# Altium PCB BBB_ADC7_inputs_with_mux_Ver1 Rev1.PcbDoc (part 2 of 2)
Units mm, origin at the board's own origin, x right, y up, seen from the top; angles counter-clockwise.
Board outline 219.96 x 100 mm, 2 copper layers (TopLayer, BottomLayer), stack 1.571 mm thick; 181 components, 118 nets, 709 pads, 266 vias.
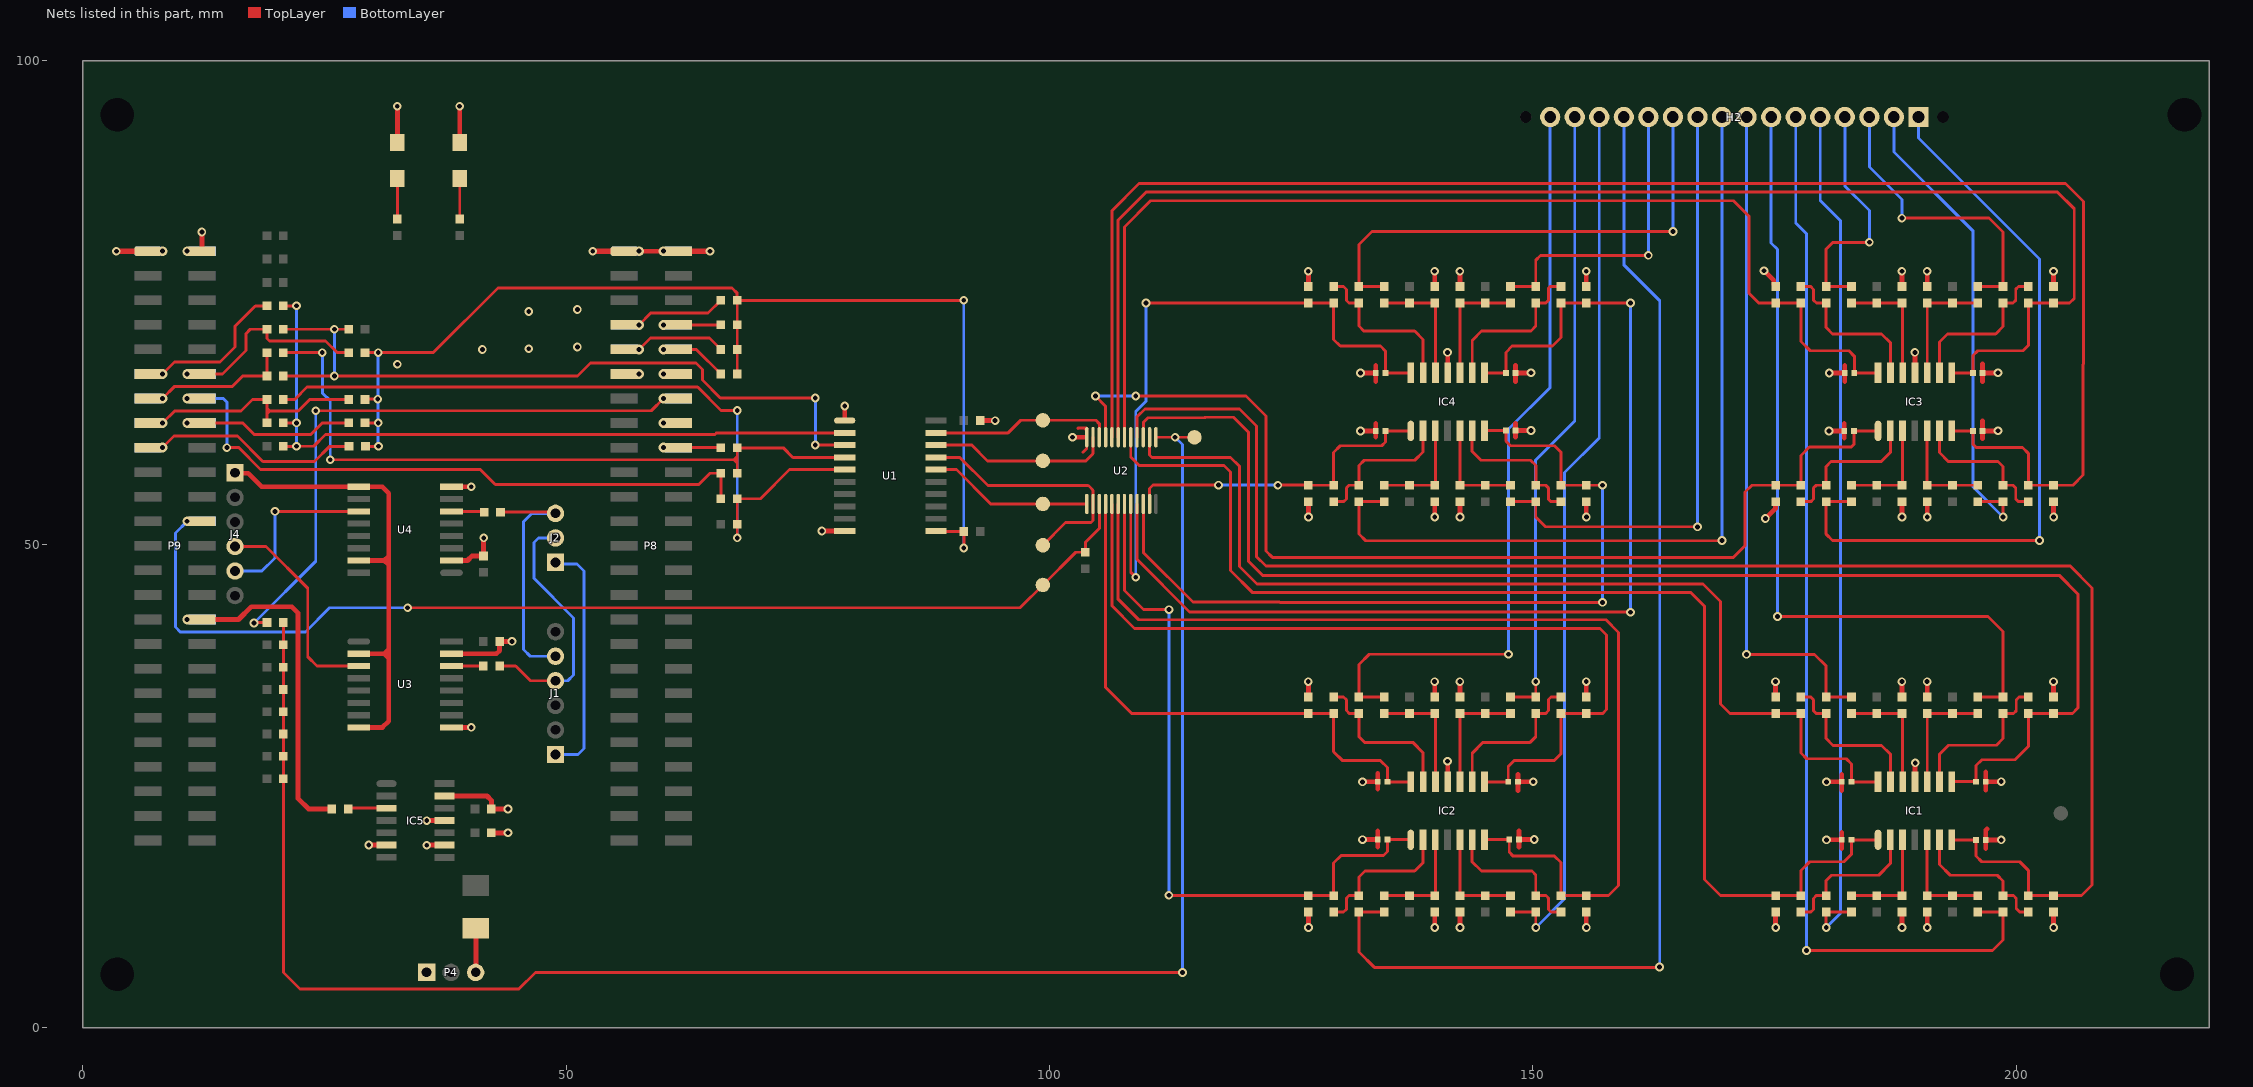
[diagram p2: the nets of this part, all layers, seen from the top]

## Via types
v1: diameter 0.9, hole 0.5, TopLayer to BottomLayer, tented both sides, 166 vias
v2: diameter 1.016, hole 0.508, TopLayer to BottomLayer, 100 vias

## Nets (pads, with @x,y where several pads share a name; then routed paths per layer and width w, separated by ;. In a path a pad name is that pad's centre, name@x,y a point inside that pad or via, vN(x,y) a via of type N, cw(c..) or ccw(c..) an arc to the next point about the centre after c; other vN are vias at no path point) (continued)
BBB_GND: C1.2 C2.2 C3.2 C4.2 C5.2 C6.2 C7.2 C8.2 C9.2 C10.2 C11.2 C12.2 C13.2 C14.2 C15.2 C16.2 C17.2 C18.2 C19.2 C20.2 C21.2 IC1.11 IC2.11 IC3.11 IC4.11 IC5.6 IC5.9 IC5.11 IC5.13 LED1.K LED2.K P4.1 P8.1 P8.2 P9.1 P9.2 R1.2 R6.2 R7.2 R11.2 R12.2 R17.2 R18.2 R22.2 R25.2 R27.2 R33.2 R35.2 R45.2 R46.2 R47.2 R48.2 R49.2 R50.2 R51.2 R52.2 R57.1 R62.1 R63.1 R68.2 R69.1 R74.1 R75.1 R80.2 R84.1 R85.1 R92.1 R93.1 U1.1 U1.10 U2.12 U3.9 U3.15 U4.2 U4.8 | length 180
  TopLayer w0.3: 102.93,61.975 102.958,62.004 103.504,62.004 ; 103.475,59.51 103.855,59.889 U2.12@103.855,61.059 103.855,61.654 ccw(c103.504,61.654) 103.504,62.004 ; U2.12@103.868,61.943 103.806,62.004 103.504,62.004 ; v1(126.769,35.777) v1@126.778,35.769 ; v1(126.769,78.233) v1@126.778,78.225 ; v1@126.778,10.358 v1(126.786,10.35) ; v1@126.778,52.814 v1(126.786,52.806) ; v1(132.167,61.704) v1@132.175,61.712 ; v1(132.167,67.711) v1@132.175,67.719 ; v1(132.372,19.436) v1@132.381,19.444 ; v1(132.372,25.408) v1@132.381,25.416 ; v1(139.839,35.777) v1@139.847,35.769 ; v1(139.839,78.233) v1@139.847,78.225 ; v1@139.847,10.358 v1(139.855,10.35) ; v1@139.847,52.814 v1(139.855,52.806) ; v1(142.453,35.777) v1@142.461,35.769 ; v1(142.453,78.233) v1@142.461,78.225 ; v1@142.461,10.358 v1(142.469,10.35) ; v1@142.461,52.814 v1(142.469,52.806) ; v1@149.795,61.748 v1(149.803,61.756) ; v1@149.795,67.719 v1(149.803,67.727) ; v1@150.037,25.416 v1(150.045,25.424) ; v1@150.137,19.444 v1(150.145,19.453) ; v1(155.522,35.777) v1@155.53,35.769 ; v1(155.522,78.233) v1@155.53,78.225 ; v1@155.53,10.358 v1(155.539,10.35) ; v1@155.53,52.814 v1(155.539,52.806) ; v1(175.106,35.777) v1@175.114,35.769 ; v1@175.114,10.358 v1(175.122,10.35) ; v1(180.367,19.408) v1@180.375,19.416 ; v1(180.367,25.408) v1@180.375,25.416 ; v1(180.628,61.711) v1@180.637,61.719 ; v1(180.667,67.704) v1@180.675,67.712 ; v1(188.175,35.777) v1@188.183,35.769 ; v1(188.175,78.233) v1@188.183,78.225 ; v1@188.183,10.358 v1(188.192,10.35) ; v1@188.183,52.814 v1(188.192,52.806) ; v1(190.789,35.777) v1@190.797,35.769 ; v1(190.789,78.233) v1@190.797,78.225 ; v1@190.797,10.358 v1(190.806,10.35) ; v1@190.797,52.814 v1(190.806,52.806) ; v1@198.106,61.719 v1(198.114,61.727) ; v1@198.106,67.719 v1(198.114,67.727) ; v1@198.437,19.402 v1(198.445,19.411) ; v1@198.437,25.428 v1(198.445,25.437) ; v1(203.859,35.777) v1@203.867,35.769 ; v1(203.859,78.233) v1@203.867,78.225 ; v1@203.867,10.358 v1(203.875,10.35) ; v1@203.867,52.814 v1(203.875,52.806)
  TopLayer w0.5: v1(12.313,82.296) 12.325,82.284 P9.2@12.325,80.305 ; v1@29.592,18.877 IC5.6@31.417,18.877 ; v1(32.524,95.3) 32.537,95.286 LED1.K@32.537,91.562 ; v1@35.592,18.867 IC5.9@37.417,18.867 ; v1@35.592,21.407 IC5.11@37.417,21.407 ; IC5.13@37.417,23.947 41.813,23.947 42.266,23.495 C20.2@42.266,22.606 v1(43.994,22.606) ; U3.9@38.139,31.039 40.164,31.039 v1(40.175,31.05) ; U3.15@38.139,38.659 42.786,38.659 43.116,38.989 C18.2@43.116,39.929 44.384,39.929 v1(44.399,39.944) ; U4.2@38.139,48.311 39.796,48.311 40.267,48.782 C19.2@41.456,48.782 41.456,50.631 v1(41.475,50.65) ; U4.8@38.139,55.931 40.164,55.931 v1(40.175,55.942) ; v1(38.982,95.3) 38.996,95.286 LED2.K@38.996,91.562 ; C21.2@42.266,20.137 43.984,20.137 v1(43.994,20.147) ; P8.1@56.001,80.305 v2(57.531,80.305) v2(60.071,80.305) P8.2@61.601,80.305 ; v1(76.45,51.358) U1.10@78.812,51.358 ; U1.1@78.812,62.788 78.812,64.287 v1(78.825,64.3) ; C17.2@92.835,62.788 94.362,62.788 v1(94.375,62.775) ; v1(102.374,61.059) U2.12@103.75,61.059 ; v1@126.778,10.358 R69.1@126.778,11.939 ; R12.2@126.778,34.188 v1@126.778,35.769 ; v1@126.778,52.814 R51.2@126.778,54.395 ; R47.2@126.778,76.644 v1@126.778,78.225 ; v1@132.175,61.712 C9.2@133.756,61.712 ; v1@132.175,67.719 C12.2@133.756,67.719 ; v1@132.381,19.444 C13.2@133.962,19.444 ; v1@132.381,25.416 C16.2@133.962,25.416 ; 133.756,61.075 C9.2@133.756,61.712 ; 133.756,62.472 C9.2@133.756,61.712 ; 133.756,66.833 C12.2@133.756,67.719 ; 133.756,68.48 C12.2@133.756,67.719 ; 133.962,18.684 C13.2@133.962,19.444 ; 133.962,20.331 C13.2@133.962,19.444 ; 133.962,24.655 C16.2@133.962,25.416 ; 133.962,26.302 C16.2@133.962,25.416 ; v1@139.847,10.358 R74.1@139.847,11.939 ; R17.2@139.847,34.188 v1@139.847,35.769 ; v1@139.847,52.814 R92.1@139.847,54.395 ; R33.2@139.847,76.644 v1@139.847,78.225 ; v1(141.181,27.537) 141.191,27.527 IC2.11@141.191,25.416 ; v1(141.181,69.84) 141.191,69.83 IC4.11@141.191,67.719 ; v1@142.461,10.358 R75.1@142.461,11.939 ; R18.2@142.461,34.188 v1@142.461,35.769 ; v1@142.461,52.814 R93.1@142.461,54.395 ; R35.2@142.461,76.644 v1@142.461,78.225 ; 148.214,61.1 C10.2@148.214,61.748 ; 148.214,62.508 C10.2@148.214,61.748 ; 148.214,66.833 C11.2@148.214,67.719 ; 148.214,68.48 C11.2@148.214,67.719 ; 148.456,24.53 C15.2@148.456,25.416 ; 148.456,26.177 C15.2@148.456,25.416 ; 148.556,18.684 C14.2@148.556,19.444 ; 148.556,20.331 C14.2@148.556,19.444 ; v1@149.795,61.748 C10.2@148.214,61.748 ; v1@149.795,67.719 C11.2@148.214,67.719 ; v1@150.037,25.416 C15.2@148.456,25.416 ; v1@150.137,19.444 C14.2@148.556,19.444 ; v1@155.53,10.358 R80.2@155.53,11.939 ; R22.2@155.53,34.188 v1@155.53,35.769 ; v1@155.53,52.814 R52.2@155.53,54.395 ; R48.2@155.53,76.644 v1@155.53,78.225 ; v1(173.916,78.277) 174.914,77.279 174.914,76.844 R45.2@175.114,76.644 ; v1(174.054,52.644) 175.114,53.704 R49.2@175.114,54.395 R49.2@174.979,54.26 ; v1@175.114,10.358 R57.1@175.114,11.939 ; R1.2@175.114,34.188 v1@175.114,35.769 ; v1@180.375,19.416 C5.2@181.956,19.416 ; v1@180.375,25.416 C8.2@181.956,25.416 ; v1@180.637,61.719 C1.2@182.218,61.719 ; v1@180.675,67.712 C4.2@182.256,67.712 ; 181.956,18.53 C5.2@181.956,19.416 ; 181.956,20.177 C5.2@181.956,19.416 ; 181.956,24.53 C8.2@181.956,25.416 ; 181.956,26.177 C8.2@181.956,25.416 ; 182.218,60.975 C1.2@182.218,61.719 ; 182.218,62.48 C1.2@182.218,61.719 ; 182.256,66.826 C4.2@182.256,67.712 ; 182.256,68.472 C4.2@182.256,67.712 ; v1@188.183,10.358 R62.1@188.183,11.939 ; R6.2@188.183,34.188 v1@188.183,35.769 ; v1@188.183,52.814 R84.1@188.183,54.395 ; R25.2@188.183,76.644 v1@188.183,78.225 ; v1(189.517,69.84) 189.527,69.83 IC3.11@189.527,67.719 ; IC1.11@189.527,25.416 189.527,27.352 v1(189.55,27.375) ; v1@190.797,10.358 R63.1@190.797,11.939 ; R7.2@190.797,34.188 v1@190.797,35.769 ; v1@190.797,52.814 R85.1@190.797,54.395 ; R27.2@190.797,76.644 v1@190.797,78.225 ; 196.525,60.925 C2.2@196.525,61.719 ; 196.525,62.725 C2.2@196.525,61.719 ; 196.525,66.833 C3.2@196.525,67.719 ; 196.525,68.65 C3.2@196.525,67.719 ; 196.856,18.516 C6.2@196.856,19.402 ; 196.856,24.542 C7.2@196.856,25.428 ; 196.856,26.425 C7.2@196.856,25.428 ; 196.983,20.549 196.856,20.422 C6.2@196.856,19.402 ; v1@198.106,61.719 C2.2@196.525,61.719 ; v1@198.106,67.719 C3.2@196.525,67.719 ; v1@198.437,19.402 C6.2@196.856,19.402 ; v1@198.437,25.428 C7.2@196.856,25.428 ; v1@203.867,10.358 R68.2@203.867,11.939 ; R11.2@203.867,34.188 v1@203.867,35.769 ; v1@203.867,52.814 R50.2@203.867,54.395 ; R46.2@203.867,76.644 v1@203.867,78.225
  TopLayer w0.6: v1(3.473,80.305) P9.1@6.725,80.305 P9.1@6.755,80.305 ; v1(52.749,80.305) P8.1@56.001,80.305 ; P8.2@61.601,80.305 v1(64.883,80.305)
  other v1: 35.584,18.859 29.584,18.869 35.584,21.399 32.537,68.613 41.33,70.145 46.131,70.215 51.161,70.399 46.131,74.066 51.161,74.267
  other v2: 8.255,80.305 10.795,80.305
BBB_SEL0: R107.2 R108.2 R109.2 U1.2 | length 75.9
  TopLayer w0.3: R109.2@20.746,60.122 22.025,60.122 22.028,60.125 v1(22.1,60.125) 23.889,60.125 25.104,61.339 65.389,61.339 65.568,61.518 U1.2@78.812,61.518 ; R108.2@20.746,62.543 22.025,62.543 22.028,62.546 v1(22.1,62.546) ; R107.2@20.746,74.651 22.025,74.651 22.028,74.654 v1(22.1,74.654)
  BottomLayer w0.3: v1(22.1,60.125) v1(22.1,62.546) v1(22.1,74.654)
BBB_SEL1: R110.2 R111.2 R112.2 U1.3 | length 77.4
  TopLayer w0.3: R110.2@20.746,67.386 v1(26.025,67.386) 51.161,67.386 52.518,68.743 63.432,68.743 64.1,68.075 64.1,66.973 65.948,65.125 v1(75.775,65.125) ; R111.2@20.746,72.229 R112.2@27.689,72.229 ; v1(75.775,60.248) U1.3@78.812,60.248
  BottomLayer w0.3: v1(26.025,67.386) v1(26.025,72.225) ; v1(75.775,60.248) v1(75.775,65.125)
BBB_SEL2: R113.2 R114.2 R115.2 U1.4 | length 72.3
  TopLayer w0.3: R113.2@20.746,69.808 24.772,69.808 v1(24.775,69.811) ; v1(25.6,58.725) 25.608,58.733 67.36,58.733 ; R115.2@67.703,57.333 67.703,59.076 ; 67.703,58.39 67.36,58.733 ; U1.4@78.812,58.978 73.447,58.978 72.46,59.965 R114.2@67.703,59.965 67.703,59.076 ; 67.36,58.733 67.703,59.076
  BottomLayer w0.3: v1(24.775,69.811) 24.775,65.65 25.6,64.825 v1(25.6,58.725)
BBB_SEL3: R116.2 R117.2 R118.2 U1.5 | length 78.1
  TopLayer w0.3: R116.2@20.746,64.965 21.915,64.965 23.2,66.25 63.604,66.25 66.029,63.825 v1(67.7,63.825) ; v1(67.703,50.648) R118.2@67.703,52.07 R117.2@67.703,54.702 70.102,54.702 73.108,57.708 U1.5@78.812,57.708
  BottomLayer w0.3: v1(67.7,63.825) 67.703,63.822 v1(67.703,50.648)
EN6595_2: P8.8 R120.2 | length 4.4
  TopLayer w0.3: P8.8@61.601,72.685 R120.2@66.003,72.685
  other v2: 60.071,72.685
IN0: H2.1 R81.1 R82.1 | length 77.3
  TopLayer w0.3: R82.1@182.956,54.395 R81.1@180.342,54.395 180.342,51.033 181.007,50.368 v1(202.4,50.368)
  BottomLayer w0.3: H2.1@189.89,94.183 189.89,92.01 202.4,79.5 v1(202.4,50.368)
IN1: H2.2 R87.1 R88.1 | length 50.3
  TopLayer w0.3: R87.1@196.025,54.395 R88.1@198.639,54.395 198.639,52.814 v1(198.647,52.806)
  BottomLayer w0.3: H2.2@187.35,94.183 187.35,90.575 195.55,82.375 195.55,55.903 v1(198.647,52.806)
IN2: H2.3 R28.2 R30.1 | length 31.2
  TopLayer w0.3: v1(188.175,83.725) 197.2,83.725 198.639,82.286 R30.1@198.639,76.644 R28.2@196.025,76.644
  BottomLayer w0.3: H2.3@184.81,94.183 184.81,89.015 188.175,85.65 v1(188.175,83.725)
IN3: H2.4 R23.2 R24.2 | length 25.3
  TopLayer w0.3: R24.2@182.956,76.644 R23.2@180.342,76.644 180.342,78.225 180.334,78.233 180.334,80.509 181.05,81.225 v1(184.81,81.225)
  BottomLayer w0.3: H2.4@182.27,94.183 182.27,87.055 184.81,84.515 v1(184.81,81.225)
IN4: H2.5 R59.1 R60.1 | length 89.5
  TopLayer w0.3: v1(180.35,10.35) 180.342,10.358 R59.1@180.342,11.939 R60.1@182.956,11.939
  BottomLayer w0.3: H2.5@179.73,94.183 179.73,85.545 181.825,83.45 181.825,11.825 v1(180.35,10.35)
IN5: H2.6 R65.1 R66.1 | length 113
  TopLayer w0.3: v1(178.3,7.975) 197.55,7.975 198.639,9.064 R66.1@198.639,11.939 R65.1@196.025,11.939
  BottomLayer w0.3: H2.6@177.19,94.183 177.19,83.222 178.325,82.088 178.325,8 v1(178.3,7.975)
IN6: H2.7 R8.2 R9.1 | length 85.2
  TopLayer w0.3: v1(175.3,42.525) 197.075,42.525 198.639,40.961 198.639,34.39 198.437,34.188 R8.2@196.025,34.188
  BottomLayer w0.3: H2.7@174.65,94.183 174.65,81.15 175.3,80.5 v1(175.3,42.525)
IN7: H2.8 R3.2 R4.2 | length 70.2
  TopLayer w0.3: v1(172.1,38.6) 179.15,38.6 180.342,37.408 R3.2@180.342,34.188 R4.2@182.956,34.188
  BottomLayer w0.3: v1(172.1,38.6) 172.11,38.61 H2.8@172.11,94.183
IN8: H2.9 R89.1 R90.1 | length 87.6
  TopLayer w0.3: R90.1@134.619,54.395 R89.1@132.005,54.395 132.005,51.059 132.713,50.351 169.551,50.351 v1(169.575,50.375)
  BottomLayer w0.3: H2.9@169.57,94.183 169.57,50.38 v1(169.575,50.375)
IN9: H2.10 R95.1 R96.1 | length 63.7
  TopLayer w0.3: R95.1@147.689,54.395 R96.1@150.303,54.395 150.303,52.814 151.316,51.8 167.016,51.8 v1(167.025,51.791)
  BottomLayer w0.3: v1@167.03,51.791 H2.10@167.03,94.183
IN10: H2.11 R31.2 R32.2 | length 51.9
  TopLayer w0.3: R32.2@134.619,76.644 R31.2@132.005,76.644 132.005,81.005 133.35,82.35 v1(164.5,82.35)
  BottomLayer w0.3: H2.11@164.49,94.183 164.49,82.36 v1(164.5,82.35)
IN11: H2.12 R36.2 R38.1 | length 31.5
  TopLayer w0.3: R36.2@147.689,76.644 R38.1@150.303,76.644 150.303,79.378 150.8,79.875 v1(161.95,79.875)
  BottomLayer w0.3: v1(161.95,79.875) H2.12@161.95,94.183
IN12: H2.13 R71.1 R72.1 | length 128
  TopLayer w0.3: R72.1@134.619,11.939 R71.1@132.005,11.939 132.005,7.82 133.6,6.225 163.075,6.225 v1(163.1,6.25)
  BottomLayer w0.3: H2.13@159.41,94.183 159.41,78.895 163.125,75.18 163.125,6.275 v1(163.1,6.25)
IN13: H2.14 R77.1 R78.1 | length 90.8
  TopLayer w0.3: R77.1@147.689,11.939 R78.1@150.303,11.939 150.303,10.358 v1(150.311,10.35)
  BottomLayer w0.3: v1(150.311,10.35) 153.276,13.315 153.276,57.399 156.87,60.994 H2.14@156.87,94.183
IN14: H2.15 R19.2 R20.1 | length 64.3
  TopLayer w0.3: R19.2@147.689,34.188 R20.1@150.303,34.188 150.303,35.769 v1(150.294,35.777)
  BottomLayer w0.3: v1(150.294,35.777) 150.294,58.718 154.33,62.754 H2.15@154.33,94.183
IN15: H2.16 R14.2 R15.2 | length 79.2
  TopLayer w0.3: R15.2@134.619,34.188 R14.2@132.005,34.188 132.005,37.543 133.073,38.61 v1(147.485,38.61)
  BottomLayer w0.3: v1(147.485,38.61) 147.485,61.91 151.79,66.215 H2.16@151.79,94.183
LATCH1: R97.1 R119.1 R120.1 R121.1 R122.1 R123.1 R126.1 R128.1 R129.1 U1.11 | length 117.4
  TopLayer w0.3: R126.1@29.2,64.965 29.163,65.001 30.442,65.001 30.445,65.004 v1(30.517,65.004) ; R123.1@29.2,69.808 30.479,69.808 30.482,69.811 v1(30.554,69.811) 36.257,69.811 42.946,76.5 67.141,76.5 67.692,75.95 67.692,75.236 R119.1@67.703,75.225 ; R129.1@29.236,60.122 30.515,60.122 30.518,60.125 v1(30.59,60.125) ; R128.1@29.236,62.507 R128.1@29.2,62.543 30.479,62.543 30.482,62.546 v1(30.554,62.546) ; R122.1@67.703,67.605 R121.1@67.703,70.145 R120.1@67.703,72.685 R119.1@67.703,75.225 ; U1.11@88.264,51.358 88.305,51.317 R97.1@91.135,51.317 91.135,49.61 v1(91.125,49.6) ; v1(91.135,75.225) R119.1@67.703,75.225
  BottomLayer w0.3: v1(30.554,69.811) v1(30.554,62.546) 30.554,60.161 v1(30.59,60.125) ; v1(91.125,49.6) 91.125,75.216 v1(91.135,75.225)
NetD03_1: D03.1 P4.3 | length 4.5
  TopLayer w0.5: P4.3@40.665,5.729 D03.1@40.665,10.261
NetIC1_2: IC1.2 R58.1 R59.2 | length 15.4
  TopLayer w0.3: R58.1@177.728,11.939 178.756,11.939 179.025,12.208 179.025,13.35 179.314,13.639 R59.2@180.342,13.639 180.342,15.197 180.895,15.75 185.776,15.75 186.977,16.951 IC1.2@186.977,19.416
NetIC1_3: IC1.3 R60.2 R61.2 R62.2 | length 11
  TopLayer w0.3: R60.2@182.956,13.639 R61.2@185.57,13.639 R62.2@188.183,13.639 188.247,13.703 IC1.3@188.247,19.416
NetIC1_5: IC1.5 R63.2 R64.2 R65.2 | length 11
  TopLayer w0.3: IC1.5@190.787,19.416 190.787,13.65 R63.2@190.797,13.639 R64.2@193.411,13.639 R65.2@196.025,13.639
NetIC1_6: IC1.6 R66.2 R67.2 | length 15.3
  TopLayer w0.3: IC1.6@192.057,19.416 192.057,16.871 193.178,15.75 198.04,15.75 198.639,15.151 R66.2@198.639,13.639 199.713,13.639 200.003,13.35 200.003,12.301 200.364,11.939 R67.2@201.253,11.939
NetIC1_9: IC1.9 R9.2 R10.2 | length 16.7
  TopLayer w0.3: IC1.9@192.067,25.416 192.067,28.267 193,29.2 197.956,29.2 198.639,29.883 R9.2@198.639,32.488 199.721,32.488 200.003,32.769 200.003,33.891 200.3,34.188 R10.2@201.253,34.188
NetIC1_10: IC1.10 R7.1 R8.1 R39.1 | length 12.3
  TopLayer w0.3: IC1.10@190.797,25.416 190.797,32.488 R39.1@193.411,32.488 R8.1@196.025,32.488
NetIC1_12: IC1.12 R4.1 R5.1 R6.1 | length 12.3
  TopLayer w0.3: R4.1@182.956,32.488 R5.1@185.57,32.488 R6.1@188.183,32.488 188.257,32.414 IC1.12@188.257,25.416
NetIC1_13: IC1.13 R2.2 R3.1 | length 16.8
  TopLayer w0.3: R2.2@177.728,34.188 178.755,34.188 179.045,33.899 179.045,32.757 179.314,32.488 R3.1@180.342,32.488 180.342,29.883 181.05,29.175 186.075,29.175 186.987,28.263 IC1.13@186.987,25.416
NetIC2_2: IC2.2 R70.1 R71.2 | length 15.5
  TopLayer w0.3: R70.1@129.391,11.939 130.419,11.939 130.708,12.229 130.708,13.37 130.977,13.639 R71.2@132.005,13.639 132.005,15.555 132.625,16.175 137.775,16.175 138.641,17.041 IC2.2@138.641,19.416
NetIC2_3: IC2.3 R72.2 R73.2 R74.2 | length 11
  TopLayer w0.3: R72.2@134.619,13.639 R73.2@137.233,13.639 R74.2@139.847,13.639 139.911,13.703 IC2.3@139.911,19.416
NetIC2_5: IC2.5 R75.2 R76.2 R77.2 | length 11
  TopLayer w0.3: IC2.5@142.451,19.416 142.451,13.65 R75.2@142.461,13.639 R76.2@145.075,13.639 R77.2@147.689,13.639
NetIC2_6: IC2.6 R78.2 R79.2 | length 15.6
  TopLayer w0.3: IC2.6@143.721,19.416 143.721,17.129 144.675,16.175 149.903,16.175 150.303,15.775 R78.2@150.303,13.639 151.35,13.639 151.619,13.37 151.619,12.208 151.888,11.939 R79.2@152.916,11.939
NetIC2_9: IC2.9 R20.2 R21.2 | length 16.6
  TopLayer w0.3: IC2.9@143.731,25.416 143.731,28.378 144.853,29.5 149.725,29.5 150.3,30.075 150.3,32.485 R20.2@150.303,32.488 151.33,32.488 151.619,32.777 151.619,33.919 151.888,34.188 R21.2@152.916,34.188
NetIC2_10: IC2.10 R18.1 R19.1 R40.1 | length 12.3
  TopLayer w0.3: IC2.10@142.461,25.416 142.461,32.488 R40.1@145.075,32.488 R19.1@147.689,32.488
NetIC2_12: IC2.12 R15.1 R16.1 R17.1 | length 12.3
  TopLayer w0.3: R15.1@134.619,32.488 R16.1@137.233,32.488 R17.1@139.847,32.488 139.921,32.414 IC2.12@139.921,25.416
NetIC2_13: IC2.13 R13.2 R14.1 | length 16.7
  TopLayer w0.3: R13.2@129.391,34.188 130.419,34.188 130.708,33.899 130.708,32.777 130.998,32.488 R14.1@132.005,32.488 132.014,32.48 132.014,30.075 132.589,29.5 137.578,29.5 138.651,28.427 IC2.13@138.651,25.416
NetIC3_2: IC3.2 R53.2 R81.2 | length 15.4
  TopLayer w0.3: R53.2@177.728,54.395 178.755,54.395 179.045,54.684 179.045,55.826 179.314,56.095 R81.2@180.342,56.095 180.342,58.042 180.85,58.55 186.05,58.55 186.977,59.477 IC3.2@186.977,61.719
NetIC3_3: IC3.3 R82.2 R83.2 R84.2 | length 10.9
  TopLayer w0.3: R82.2@182.956,56.095 R83.2@185.57,56.095 R84.2@188.183,56.095 188.247,56.159 IC3.3@188.247,61.719
NetIC3_5: IC3.5 R85.2 R86.2 R87.2 | length 10.9
  TopLayer w0.3: IC3.5@190.787,61.719 190.787,56.105 R85.2@190.797,56.095 R86.2@193.411,56.095 R87.2@196.025,56.095
NetIC3_6: IC3.6 R54.1 R88.2 | length 15.4
  TopLayer w0.3: IC3.6@192.057,61.719 192.057,59.468 192.975,58.55 198.131,58.55 198.639,58.042 R88.2@198.639,56.095 199.666,56.095 199.956,55.806 199.956,54.664 200.225,54.395 R54.1@201.253,54.395
NetIC3_9: IC3.9 R30.2 R42.1 | length 16.8
  TopLayer w0.3: IC3.9@192.067,67.719 192.067,70.912 192.905,71.75 197.875,71.75 198.639,72.514 R30.2@198.639,74.944 199.666,74.944 199.956,75.233 199.956,76.375 200.225,76.644 R42.1@201.253,76.644
NetIC3_10: IC3.10 R27.1 R28.1 R29.1 | length 12.5
  TopLayer w0.3: IC3.10@190.797,67.719 R27.1@190.797,74.944 R29.1@193.411,74.944 R28.1@196.025,74.944
NetIC3_12: IC3.12 R24.1 R25.1 R26.1 | length 12.5
  TopLayer w0.3: R24.1@182.956,74.944 R26.1@185.57,74.944 R25.1@188.183,74.944 188.257,74.87 IC3.12@188.257,67.719
NetIC3_13: IC3.13 R23.1 R41.2 | length 16.9
  TopLayer w0.3: R41.2@177.728,76.644 178.756,76.644 179.045,76.355 179.045,75.233 179.334,74.944 R23.1@180.342,74.944 180.342,72.408 181,71.75 186.081,71.75 186.987,70.844 IC3.13@186.987,67.719
NetIC4_2: IC4.2 R55.2 R89.2 | length 15.4
  TopLayer w0.3: R55.2@129.391,54.395 130.419,54.395 130.708,54.684 130.708,55.826 130.977,56.095 R89.2@132.005,56.095 132.005,58.13 132.55,58.675 137.775,58.675 138.641,59.541 IC4.2@138.641,61.719
NetIC4_3: IC4.3 R90.2 R91.2 R92.2 | length 10.9
  TopLayer w0.3: R90.2@134.619,56.095 R91.2@137.233,56.095 R92.2@139.847,56.095 139.911,56.159 IC4.3@139.911,61.719
NetIC4_5: IC4.5 R93.2 R94.2 R95.2 | length 10.9
  TopLayer w0.3: IC4.5@142.451,61.719 142.451,56.105 R93.2@142.461,56.095 R94.2@145.075,56.095 R95.2@147.689,56.095
NetIC4_6: IC4.6 R56.1 R96.2 | length 15.4
  TopLayer w0.3: IC4.6@143.721,61.719 143.721,59.579 144.625,58.675 149.766,58.675 150.311,58.13 150.311,56.103 R96.2@150.303,56.095 151.331,56.095 151.6,55.826 151.6,54.684 151.889,54.395 R56.1@152.916,54.395
NetIC4_9: IC4.9 R38.2 R44.1 | length 17
  TopLayer w0.3: IC4.9@143.731,67.719 143.731,71.081 144.7,72.05 149.8,72.05 150.303,72.553 R38.2@150.303,74.944 151.331,74.944 151.6,75.213 151.6,76.453 151.79,76.644 R44.1@152.916,76.644
NetIC4_10: IC4.10 R35.1 R36.1 R37.1 | length 12.5
  TopLayer w0.3: IC4.10@142.461,67.719 R35.1@142.461,74.944 R37.1@145.075,74.944 R36.1@147.689,74.944
NetIC4_12: IC4.12 R32.1 R33.1 R34.1 | length 12.5
  TopLayer w0.3: R32.1@134.619,74.944 R34.1@137.233,74.944 R33.1@139.847,74.944 139.921,74.87 IC4.12@139.921,67.719
NetIC4_13: IC4.13 R31.1 R43.2 | length 17
  TopLayer w0.3: R43.2@129.391,76.644 130.419,76.644 130.708,76.354 130.708,75.213 130.977,74.944 R31.1@132.005,74.944 132.005,72.553 132.508,72.05 137.775,72.05 138.651,71.174 IC4.13@138.651,67.719
NetIC5_3: IC5.3 R130.2 | length 4
  TopLayer w0.3: R130.2@27.444,22.606 27.525,22.687 IC5.3@31.417,22.687
NetJ4_4: J4.4 U3.3 | length 22.1
  TopLayer w0.3: J4.4@15.748,49.759 18.941,49.759 23.269,45.431 23.269,38.346 24.226,37.389 U3.3@28.539,37.389
NetJ4_5: J4.5 U4.11 | length 18.2
  TopLayer w0.3: v1(19.875,53.391) U4.11@28.539,53.391
  BottomLayer w0.3: J4.5@15.748,47.219 18.519,47.219 19.875,48.575 v1(19.875,53.391)
NetLED1_A: LED1.A R131.1 | length 4.2
  TopLayer w0.3: R131.1@32.537,83.629 LED1.A@32.537,87.812
NetLED2_A: LED2.A R132.1 | length 4.2
  TopLayer w0.3: R132.1@38.996,83.629 LED2.A@38.996,87.812
NetR133_1: R133.1 U3.14 | length 3.3
  TopLayer w0.3: U3.14@38.139,37.389 R133.1@41.416,37.389
NetR134_1: R134.1 U4.6 | length 3.4
  TopLayer w0.3: U4.6@38.139,53.391 41.441,53.391 R134.1@41.517,53.315
OCO_ISO: P8.14 R99.1 | length 62.4
  TopLayer w0.3: v1(17.715,41.851) 17.757,41.894 R99.1@19.046,41.894 ; v1(24.1,63.8) 58.806,63.8 v2(60.071,65.065)
  BottomLayer w0.3: v1(17.715,41.851) 24.1,48.237 v1(24.1,63.8)
P8_7: P8.7 R119.2 | length 9.5
  TopLayer w0.3: v2(57.531,72.685) 58.746,73.9 64.677,73.9 R119.2@66.003,75.225
P8_9: P8.9 R121.2 | length 9.4
  TopLayer w0.3: v2(57.531,70.145) 58.711,71.325 64.823,71.325 R121.2@66.003,70.145
P8_10: P8.10 R122.2 | length 5.5
  TopLayer w0.3: P8.10@61.601,70.145 63.463,70.145 R122.2@66.003,67.605
  other v2: 60.071,70.145
P8_12: P8.12
  other v2: 60.071,67.605
P8_16: P8.16
  other v2: 60.071,62.525
P8_18: P8.18 R114.1 | length 4.4
  TopLayer w0.3: P8.18@61.601,59.985 65.982,59.985 R114.1@66.003,59.965
  other v2: 60.071,59.985
P9-24: P9.24 R98.1 TP0.1 U2.15 | length 114.8
  TopLayer w0.3: v1(33.6,43.419) 96.96,43.419 TP0.1@99.316,45.775 102.706,49.164 R98.1@103.705,49.164 103.705,50.175 105.155,51.625 U2.15@105.155,54.159
  BottomLayer w0.3: v2(10.795,52.365) 9.575,51.145 9.575,41.425 10.075,40.925 23.025,40.925 25.519,43.419 v1(33.6,43.419)
P9_11: P9.11 R107.1 | length 15
  TopLayer w0.3: v2(8.255,67.605) 9.5,68.85 14.191,68.85 15.748,70.407 15.748,72.55 17.848,74.651 R107.1@19.046,74.651
P9_12: P9.12 R111.1 R123.2 | length 19.9
  TopLayer w0.3: P9.12@12.325,67.605 14.462,67.605 16.875,70.019 16.875,71.775 17.329,72.229 R111.1@19.046,72.229 19.046,71.279 19.3,71.025 25.119,71.025 26.336,69.808 R123.2@27.689,69.808
  other v2: 10.795,67.605
P9_13: P9.13 R110.1 R113.1 | length 14.2
  TopLayer w0.3: v2(8.255,65.065) 9.515,66.325 15.475,66.325 16.536,67.386 R110.1@19.046,67.386 R113.1@19.046,69.808
P9_14: P9.14 R115.1 R117.1 | length 63.2
  TopLayer w0.3: v1(14.9,59.985) 16.131,59.985 18.384,57.733 41.117,57.733 42.675,56.175 63.725,56.175 64.883,57.333 R115.1@66.003,57.333 R117.1@66.003,54.702
  BottomLayer w0.3: P9.14@12.355,65.065 14.535,65.065 14.925,64.675 14.925,60.01 v1(14.9,59.985)
  other v2: 10.795,65.065
P9_15: P9.15 R108.1 R116.1 R126.2 | length 23.7
  TopLayer w0.3: v2(8.255,62.525) 9.505,63.775 16.375,63.775 17.565,64.965 R116.1@19.046,64.965 19.046,64.076 ; R108.1@19.046,62.543 19.046,63.474 ; R126.2@27.5,64.965 23.466,64.965 22.277,63.775 19.347,63.775 ; 19.046,63.474 19.046,64.076 ; 19.046,63.474 19.347,63.775 ; 19.046,64.076 19.347,63.775
P9_16: P9.16 R128.2 | length 16.2
  TopLayer w0.3: P9.16@12.325,62.525 16.55,62.525 17.752,61.323 23.548,61.323 24.768,62.543 R128.2@27.5,62.543
  other v2: 10.795,62.525
P9_17: P9.17 R129.2 | length 21.5
  TopLayer w0.3: v2(8.255,59.985) 9.445,61.175 15.996,61.175 18.621,58.55 23.975,58.55 25.547,60.122 R129.2@27.536,60.122
P811: P8.11
  other v2: 57.531,67.605
PC_GND: J4.1 U3.2 U3.8 U4.9 U4.15 | length 52.5
  TopLayer w0.5: J4.1@15.748,57.379 15.8,57.326 17.105,57.326 18.501,55.931 U4.9@28.539,55.931 30.986,55.931 31.65,55.267 31.65,39.104 ; U3.8@28.539,31.039 30.994,31.039 31.65,31.694 31.65,38.213 ; U3.2@28.539,38.659 31.205,38.659 ; U4.15@28.539,48.311 31.205,48.311 ; 31.205,38.659 31.65,39.104 ; 31.205,38.659 31.65,38.213 ; 31.205,48.311 31.65,48.756 31.65,47.865 31.205,48.311 ; 31.65,38.213 31.65,39.104
PIN1: J1.1 J2.1 | length 24.9
  BottomLayer w0.3: J1.1@48.895,28.245 51.22,28.245 51.85,28.875 51.85,47.226 51.126,47.95 49.053,47.95 J2.1@48.895,48.108
PIN2: J1.4 J2.2 R133.2 | length 26.4
  TopLayer w0.3: R133.2@43.116,37.389 44.78,37.389 46.304,35.865 J1.4@48.895,35.865
  BottomLayer w0.3: J1.4@48.895,35.865 50.165,35.865 50.775,36.475 50.775,42.375 46.675,46.475 46.675,50.175 47.148,50.648 J2.2@48.895,50.648
PIN3: J1.5 J2.3 R134.2 | length 26.2
  TopLayer w0.3: R134.2@43.217,53.315 48.768,53.315 J2.3@48.895,53.188
  BottomLayer w0.3: J1.5@48.895,38.405 46.295,38.405 45.6,39.1 45.6,52.325 46.463,53.188 J2.3@48.895,53.188
S0: C1.1 IC3.1 R49.1 R53.1 U2.9 | length 112
  TopLayer w0.3: v1(104.75,65.325) 105.805,64.27 U2.9@105.805,61.059 ; v1(108.925,65.325) 120.325,65.325 122.4,63.25 122.4,49.287 123.051,48.636 170.761,48.636 171.95,49.825 171.95,55.381 172.664,56.095 R49.1@175.114,56.095 R53.1@177.728,56.095 177.728,59.178 178.6,60.05 182.938,60.05 183.218,60.33 C1.1@183.218,61.719 IC3.1@185.707,61.719
  BottomLayer w0.3: v1(104.75,65.325) v1(108.925,65.325)
S1: C2.1 IC3.7 R50.1 R54.2 U2.8 | length 173.3
  TopLayer w0.3: U2.8@106.455,61.059 106.455,84.495 109.267,87.307 205.104,87.307 206.975,85.436 206.975,68.65 206.925,68.6 206.925,57.15 205.87,56.095 R50.1@203.867,56.095 R54.2@201.253,56.095 201.253,59.397 200.665,59.985 195.872,59.985 195.525,60.332 C2.1@195.525,61.719 IC3.7@193.327,61.719
S2: C3.1 IC3.8 R42.2 R46.1 U2.7 | length 152
  TopLayer w0.3: U2.7@107.105,61.059 107.105,83.545 109.971,86.411 204.275,86.411 206,84.686 206,75.425 205.519,74.944 R46.1@203.867,74.944 R42.2@201.253,74.944 201.253,70.553 200.704,70.004 196.025,70.004 195.525,69.504 C3.1@195.525,67.719 IC3.8@193.337,67.719
S3: C4.1 IC3.14 R41.1 R45.1 U2.6 | length 116.2
  TopLayer w0.3: U2.6@107.755,61.059 107.755,82.82 110.46,85.525 170.75,85.525 172.352,83.923 172.352,75.952 173.361,74.944 R45.1@175.114,74.944 R41.1@177.728,74.944 177.728,70.975 178.698,70.004 182.696,70.004 183.256,69.444 C4.1@183.256,67.712 185.7,67.712 IC3.14@185.707,67.719
S4: C5.1 IC1.1 R57.2 R58.2 U2.5 | length 125.5
  TopLayer w0.3: U2.5@108.405,61.059 108.405,59.02 109.275,58.15 118.05,58.15 118.725,57.475 118.725,47.266 120.973,45.018 166.307,45.018 167.75,43.575 167.75,15.3 169.411,13.639 R57.2@175.114,13.639 R58.2@177.728,13.639 177.728,16.228 178.65,17.15 182.191,17.15 182.956,17.915 C5.1@182.956,19.416 IC1.1@185.707,19.416
S5: C6.1 IC1.7 R67.1 R68.1 U2.4 | length 167.5
  TopLayer w0.3: U2.4@109.055,61.059 109.055,63.18 109.87,63.995 119.655,63.995 121.428,62.222 121.428,48.697 122.4,47.725 205.6,47.725 207.85,45.475 207.85,14.75 206.739,13.639 R68.1@203.867,13.639 R67.1@201.253,13.639 201.253,16.261 200.364,17.15 196.445,17.15 195.856,17.739 C6.1@195.856,19.402 195.842,19.416 IC1.7@193.327,19.416
S6: C7.1 IC1.8 R10.1 R11.1 U2.3 | length 144.8
  TopLayer w0.3: U2.3@109.705,61.059 109.705,62.58 110.2,63.075 116.05,63.075 116.1,63.125 119.024,63.125 120.575,61.574 120.575,48.225 122.025,46.775 204.45,46.775 206.375,44.85 206.375,33.05 205.813,32.488 R11.1@203.867,32.488 R10.1@201.253,32.488 201.253,29.078 199.876,27.701 196.457,27.701 195.856,27.1 C7.1@195.856,25.428 193.35,25.428 IC1.8@193.337,25.416
S7: C8.1 IC1.14 R1.1 R2.1 U2.2 | length 107
  TopLayer w0.3: U2.2@110.355,61.059 110.355,59.215 110.591,58.978 118.738,58.978 119.655,58.061 119.655,47.7 121.48,45.875 167.6,45.875 169.411,44.064 169.411,33.464 170.387,32.488 R1.1@175.114,32.488 R2.1@177.728,32.488 177.728,28.397 178.325,27.8 182.425,27.8 182.956,27.269 C8.1@182.956,25.416 IC1.14@185.707,25.416
S8: C9.1 IC4.1 R51.1 R55.1 U2.23 | length 33.8
  TopLayer w0.3: U2.23@110.355,54.159 110.355,55.759 110.714,56.118 117.462,56.118 v1(117.475,56.105) ; v1(123.625,56.1) 126.773,56.1 R51.1@126.778,56.095 R55.1@129.391,56.095 129.391,59.491 130.075,60.175 134.375,60.175 134.756,60.556 C9.1@134.756,61.712 137.363,61.712 IC4.1@137.371,61.719
  BottomLayer w0.3: v1(117.475,56.105) 123.62,56.105 v1(123.625,56.1)
S9: C10.1 IC4.7 R52.1 R56.2 U2.22 | length 84
  TopLayer w0.3: U2.22@109.705,54.159 109.705,49.15 114.833,44.021 123.785,44.021 123.831,43.975 v1(157.2,43.975) ; IC4.7@144.991,61.719 145.019,61.748 C10.1@147.214,61.748 147.214,60.65 147.689,60.175 152.25,60.175 152.916,59.509 R56.2@152.916,56.095 R52.1@155.53,56.095 v1(157.201,56.095)
  BottomLayer w0.3: v1(157.2,43.975) v1(157.201,56.095)
S10: C11.1 IC4.8 R44.2 R48.1 U2.21 | length 112.4
  TopLayer w0.3: U2.21@109.055,54.159 109.055,48.431 114.494,42.991 v1@160.1,42.991 ; IC4.8@145.001,67.719 C11.1@147.214,67.719 147.214,69.84 147.858,70.484 152.034,70.484 152.916,71.366 R44.2@152.916,74.944 R48.1@155.53,74.944 v1(160.1,74.944)
  BottomLayer w0.3: v1(160.1,42.962) v1(160.1,74.944)
S11: C12.1 IC4.14 R43.1 R47.1 U2.20 | length 70.5
  TopLayer w0.3: U2.20@108.405,54.159 108.405,47.103 v1(108.925,46.582) ; v1(109.975,74.944) R47.1@126.778,74.944 R43.1@129.391,74.944 129.391,71.174 130.081,70.484 134.23,70.484 134.756,69.958 C12.1@134.756,67.719 IC4.14@137.371,67.719
  BottomLayer w0.3: v1(108.925,46.582) 108.925,63.725 109.975,64.775 v1(109.975,74.944)
S12: C13.1 IC2.1 R69.2 R70.2 U2.19 | length 74.1
  TopLayer w0.3: U2.19@107.755,54.159 107.755,45.2 109.726,43.228 v1(112.364,43.228) ; v1(112.35,13.675) 112.386,13.639 R69.2@126.778,13.639 R70.2@129.391,13.639 129.391,17.016 130.175,17.8 134.55,17.8 134.962,18.212 C13.1@134.962,19.444 137.342,19.444 IC2.1@137.371,19.416
  BottomLayer w0.3: v1(112.35,13.675) 112.364,13.689 v1(112.364,43.228)
S13: C14.1 IC2.7 R79.1 R80.1 U2.18 | length 108.7
  TopLayer w0.3: U2.18@107.105,54.159 107.105,44.3 109.23,42.175 157.559,42.175 158.875,40.859 158.875,14.679 157.836,13.639 R80.1@155.53,13.639 R79.1@152.916,13.639 152.916,17.059 152.25,17.725 147.975,17.725 147.556,18.144 C14.1@147.556,19.444 145.019,19.444 IC2.7@144.991,19.416
S14: C15.1 IC2.8 R21.1 R22.1 U2.17 | length 89.8
  TopLayer w0.3: U2.17@106.455,54.159 106.455,43.62 108.8,41.275 156.95,41.275 157.632,40.593 157.632,32.893 157.227,32.488 R22.1@155.53,32.488 R21.1@152.916,32.488 152.916,28.316 152.2,27.6 148.05,27.6 147.456,27.006 C15.1@147.456,25.416 IC2.8@145.001,25.416
S15: C16.1 IC2.14 R12.1 R13.1 U2.16 | length 57.8
  TopLayer w0.3: U2.16@105.805,54.159 105.805,35.195 108.512,32.488 R12.1@126.778,32.488 R13.1@129.391,32.488 129.391,28.534 130.325,27.6 134.25,27.6 134.962,26.888 C16.1@134.962,25.416 IC2.14@137.371,25.416
SEL0: TP6.1 U1.19 U2.10 | length 19
  TopLayer w0.3: U1.19@88.264,61.518 95.724,61.518 97.022,62.816 TP6.1@99.316,62.816 104.799,62.816 105.155,62.46 U2.10@105.155,61.059
SEL1: TP1.1 U1.18 U2.11 | length 18.9
  TopLayer w0.3: U1.18@88.264,60.248 91.96,60.248 93.6,58.609 TP1.1@99.316,58.609 103.755,58.609 104.505,59.358 U2.11@104.505,61.059
SEL2: TP2.1 U1.17 U2.14 | length 27
  TopLayer w0.3: U1.17@88.264,58.978 90.722,58.978 93.623,56.077 103.998,56.077 104.124,55.951 104.505,55.57 U2.14@104.505,54.159 104.505,52.455 104.275,52.225 101.654,52.225 TP2.1@99.316,49.887
SEL3: TP3.1 U1.16 U2.13 | length 17.1
  TopLayer w0.3: U1.16@88.264,57.708 90.367,57.708 93.916,54.159 TP3.1@99.316,54.159 U2.13@103.855,54.159
SIG1: R99.2 R100.2 R101.2 R102.2 R103.2 R104.2 R105.2 R106.2 TP4.1 U2.1 | length 190.3
  TopLayer w0.3: R99.2@20.746,41.894 R104.2@20.746,39.586 R105.2@20.746,37.277 R106.2@20.746,34.969 R103.2@20.746,32.661 R102.2@20.746,30.353 R101.2@20.746,28.045 R100.2@20.746,25.736 20.746,5.704 22.475,3.975 45.1,3.975 46.825,5.7 v1(113.75,5.7) ; U2.1@111.005,61.059 v1(112.995,61.059) 114.985,61.059 TP4.1@114.998,61.046
  BottomLayer w0.3: v1(112.995,61.059) 113.75,60.304 v1(113.75,5.7)
VREF1.8: P9.32 R130.1 | length 33.9
  TopLayer w0.5: P9.32@12.325,42.205 16.105,42.205 17.425,43.525 21.625,43.525 22.277,42.873 22.277,23.68 23.35,22.606 R130.1@25.744,22.606
  other v2: 10.795,42.205
pads on no net: H2.0 IC5.7 IC5.8 IC5.14 J1.2 J1.3 J1.6 J4.2 J4.6 P8.3 P8.4 P8.5 P8.6 P8.13 P8.15 P8.17 P8.19 P8.20 P8.21 P8.22 P8.23 P8.24 P8.25 P8.26 P8.27 P8.28 P8.29 P8.30 P8.31 P8.32 P8.33 P8.34 P8.35 P8.36 P8.37 P8.38 P8.39 P8.40 P8.41 P8.42 P8.43 P8.44 P8.45 P8.46 P8.47 P8.48 P8.49 P8.50 P9.9 P9.10 P9.18 P9.19 P9.20 P9.21 P9.22 P9.23 P9.25 P9.26 P9.27 P9.28 P9.29 P9.30 P9.31 P9.34 P9.41 P9.42 P9.43 P9.44 P9.45 P9.46 P9.47 P9.48 P9.49 P9.50 R109.1 R112.1 R118.1 U1.6 U1.7 U1.8 U1.9 U1.12 U1.13 U1.14 U1.15 U3.4 U3.5 U3.6 U3.7 U3.10 U3.11 U3.12 U3.13 U4.3 U4.4 U4.5 U4.7 U4.10 U4.12 U4.13 U4.14
copper on no net:
  other v2: 8.255,19.345 10.795,19.345 57.531,19.345 60.071,19.345 8.255,21.885 10.795,21.885 57.531,21.885 60.071,21.885 8.255,24.425 10.795,24.425 57.531,24.425 60.071,24.425 8.255,26.965 10.795,26.965 57.531,26.965 60.071,26.965 8.255,29.505 10.795,29.505 57.531,29.505 60.071,29.505 57.531,32.045 60.071,32.045 57.531,34.585 60.071,34.585 57.531,37.125 60.071,37.125 10.795,39.665 57.531,39.665 60.071,39.665 8.255,42.205 57.531,42.205 60.071,42.205 8.255,44.745 10.795,44.745 57.531,44.745 60.071,44.745 8.255,47.285 10.795,47.285 57.531,47.285 60.071,47.285 8.255,49.825 10.795,49.825 57.531,49.825 60.071,49.825 8.255,52.365 57.531,52.365 60.071,52.365 8.255,54.905 10.795,54.905 57.531,54.905 60.071,54.905 8.255,57.445 10.795,57.445 57.531,57.445 60.071,57.445 10.795,59.985 57.531,59.985 57.531,62.525 57.531,65.065 8.255,70.145 10.795,70.145 57.531,75.225 60.071,75.225 57.531,77.765 60.071,77.765

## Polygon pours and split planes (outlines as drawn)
BBB_GND on TopLayer "BBB_GND_L01_P004" (solid, remove dead copper, pour order 4): 213.825,10.35 ccw(c213.825,8.45) 211.925,8.45 211.925,3.028 211.339,3.023 7.95,3.023 7.95,7.75 ccw(c6.063,7.763) 6.075,9.65 5.875,9.65 1.93,9.65 1.93,90.075 5.7,90.075 5.98,90.075 ccw(c5.98,92.35) 8.255,92.35 8.255,97.003 212.45,97.003 212.45,91.838 ccw(c214.688,91.838) 214.688,89.6 218.465,89.6 218.465,10.35
BBB_GND on BottomLayer "BBB_GND_L02_P003" (solid, remove dead copper, pour order 3): 213.825,10.35 ccw(c213.825,8.45) 211.925,8.45 211.925,3.028 211.339,3.023 7.95,3.023 7.95,7.75 ccw(c6.063,7.763) 6.075,9.65 5.875,9.65 1.93,9.65 1.93,90.075 5.7,90.075 5.98,90.075 ccw(c5.98,92.35) 8.255,92.35 8.255,97.003 212.45,97.003 212.45,91.838 ccw(c214.688,91.838) 214.688,89.6 218.465,89.6 218.465,10.35

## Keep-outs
KeepOutLayer:
  lines w0.203: 1.93,8.55 1.93,91.425 6.6,91.425 6.6,97.003 214.45,97.003 214.45,91.425 218.465,91.425 218.465,8.4 213.75,8.4 213.75,3.023 6.575,3.023 6.575,8.55 1.93,8.55

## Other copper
TopLayer:
  pour cut-out: 54.123,79.1 54.123,18.337 63.539,18.337 63.539,79.1
  pour cut-out: 4.847,79.1 4.847,18.337 14.263,18.337 14.263,79.1
  text "'.Layer_Name'" at 187.556,-11.738 h5
BottomLayer:
  pour cut-out: 54.123,79.1 54.123,18.337 63.539,18.337 63.539,79.1
  pour cut-out: 4.847,79.1 4.847,18.337 14.263,18.337 14.263,79.1
  text "'.Layer_Name'" at 210.556,-17.738 h5

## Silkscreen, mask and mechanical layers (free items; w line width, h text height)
TopOverlay:
  circle w0.254: c217.424,94.412 r2.857
  circle w0.254: c216.637,5.512 r2.857
  circle w0.254: c3.556,94.412 r2.857
  circle w0.254: c3.556,5.512 r2.857
  rectangle: 103.2,92.71 122.25,97.79
  rectangle: 103.2,86.385 122.25,91.465
  text "S/N" at 97.587,94.056 h1.91
  text "REV" at 97.663,87.757 h1.91
Mechanical1:
  the board outline again, w0.5
DrillDrawing:
  text ".Legend" at 234.137,2.921 h5

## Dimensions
3.556,5.512 to 3.556,94.412 on Mechanical1
3.556,94.412 to 217.424,94.412 on Mechanical1
0,100 to 0,0 on Mechanical1
0,100 to 219.964,100 on Mechanical1
3.556,-0.508 to 0,0 on Mechanical4
-0.508,5.512 to 0,0 on Mechanical4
